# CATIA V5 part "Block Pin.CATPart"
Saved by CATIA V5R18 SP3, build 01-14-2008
Part number: Turn Table Guide
Bounding box of the stored display mesh (mm): x 0 to 340, y -39.996 to 39.996, z -39.998 to 39.998
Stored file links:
  E:\#00 CATIA V5 Movie\#03 CATIA V5 Data\#07 KIN\Balance Unit (1)\Block Pin.CATPart
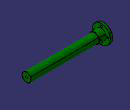
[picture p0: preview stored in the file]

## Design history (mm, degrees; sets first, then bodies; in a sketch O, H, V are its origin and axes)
Body1 "PartBody" (main body)
  Solid1: solid without history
